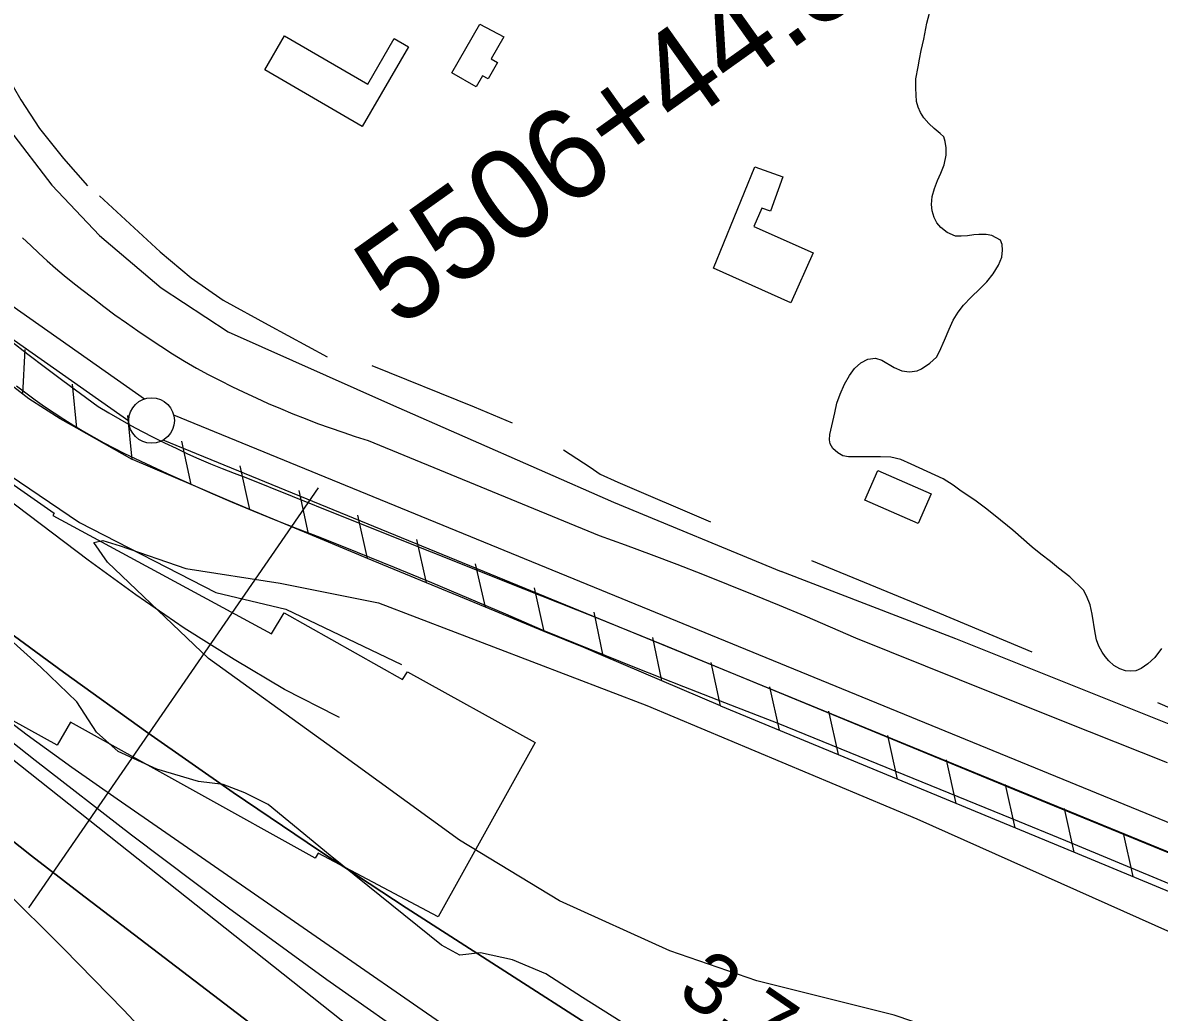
# Model space of a CAD drawing. Extents: x 3567028 to 3605064, y 510945 to 536587.
# Drawn here: x 3580256 to 3581504, y 529130 to 530217 of the extents above; entities that cross this region are included whole.
import ezdxf

# ---------------------------------------------------------------- set-up
doc = ezdxf.new("R2010")
doc.units = 0
for name, color, linetype in [('V-BLDG-OTLN', 7, 'Continuous'), ('V-FLOD-BASE', 7, 'Continuous'), ('V-LEVE-TOET', 7, 'Continuous'), ('V-RIVR-EDGE', 7, 'Continuous'), ('V-RIVR-RANG', 7, 'Continuous'), ('V-ROAD-CNTR', 7, 'Continuous'), ('V-RRAP-FSHR', 7, 'Continuous'), ('V-RRAP-RVMT', 7, 'Continuous'), ('V-SITE-VEGE', 7, 'Continuous'), ('V-SURV-IDEN', 7, 'Continuous'), ('V-SURV-LINE', 7, 'Continuous'), ('V-TOPO-DPTH', 7, 'Continuous'), ('V-TOPO-MINR', 7, 'Continuous'), ('V-TOPO-SHOR', 7, 'Continuous'), ('V-TOPO-WATR', 7, 'Continuous')]:
    doc.layers.add(name, color=color, linetype=linetype)

msp = doc.modelspace()

# ---------------------------------------------------------------- linework, layer by layer
at = {"layer": 'V-BLDG-OTLN'}
for points in [[(3580784.2, 530201), (3580770.2, 530176.8), (3580777.1, 530172.8), (3580766.7, 530154.8), (3580760.5, 530158.3), (3580753.6, 530146.3), (3580727, 530161.6), (3580757.8, 530214.9)], [(3580628.6, 530102.8), (3580521.8, 530164.8), (3580543.3, 530202), (3580634.6, 530149.1), (3580663.8, 530199.3), (3580679.4, 530190.2)], [(3581014.1, 529947), (3581059.6, 530058.3), (3581090.2, 530047.3), (3581076.8, 530009.8), (3581067.4, 530013), (3581058.5, 529992.9), (3581123.6, 529963.9), (3581099.2, 529909.2)], [(3581253.3, 529699.5), (3581238.9, 529666.8), (3581180.3, 529692.6), (3581194.6, 529725)]]:
    msp.add_lwpolyline(points, close=True, dxfattribs=at)
at = {"layer": 'V-FLOD-BASE'}
for points in [[(3580242.8, 529867.4), (3580261.7, 529852.7), (3580280.8, 529838.1), (3580299.9, 529823.7), (3580319.2, 529809.5), (3580338.6, 529795.4), (3580350.6, 529788.3), (3580362.6, 529781.3), (3580374.7, 529774.6), (3580386.9, 529768), (3580399.2, 529761.6), (3580411.6, 529755.4), (3580424.2, 529749.4), (3580436.8, 529743.5), (3580449.4, 529737.9), (3580462.2, 529732.4), (3580475, 529727.2), (3580488, 529722.1), (3580501, 529717.3), (3580602.5, 529676.4)], [(3580602.5, 529676.4), (3580704.2, 529635.8), (3580805.9, 529595.3), (3580883.5, 529564.3), (3580961, 529532.9), (3581038.3, 529501.3), (3581115.6, 529469.5), (3581232.6, 529421), (3581349.6, 529372.8), (3581466.8, 529324.8), (3581564, 529284.8), (3581661, 529244.7), (3581758, 529204.3), (3581854.8, 529163.6)]]:
    msp.add_lwpolyline(points, dxfattribs=at)
at = {"layer": 'V-LEVE-TOET'}
for points in [[(3580255.8, 529980.5), (3580264.7, 529971.9), (3580273.7, 529963.5), (3580282.8, 529955.2), (3580292.1, 529947.1), (3580301.5, 529939.2), (3580311, 529931.4), (3580320.7, 529923.8), (3580332.8, 529914.4), (3580344.9, 529905.1), (3580357.2, 529896), (3580369.7, 529887.1), (3580382.2, 529878.4), (3580394.9, 529869.8), (3580407.6, 529861.4), (3580420.5, 529853.2), (3580433.6, 529845.2), (3580446.7, 529837.3), (3580459.6, 529830.4), (3580472.6, 529823.7), (3580485.6, 529817.2), (3580498.8, 529810.9), (3580512.1, 529804.7), (3580525.4, 529798.7), (3580538.8, 529793), (3580552.4, 529787.4), (3580565.9, 529782), (3580579.6, 529776.8), (3580593.4, 529771.8), (3580607.2, 529767.1), (3580621, 529762.5), (3580635, 529758.1), (3580719.5, 529723.1), (3580804.1, 529688.4), (3580888.8, 529653.8), (3580917.2, 529643.4), (3580945.6, 529632.9), (3580973.9, 529622.1), (3581002.1, 529611.1), (3581030.3, 529600), (3581058.4, 529588.7), (3581086.3, 529577.1), (3581114.3, 529565.4), (3581142.1, 529553.5), (3581169.9, 529541.4), (3581284, 529495.8), (3581398.1, 529450.1), (3581512.3, 529404.5)], [(3580249.1, 529817.9), (3580259.3, 529810.2), (3580269.6, 529802.7), (3580280, 529795.4), (3580290.5, 529788.3), (3580301.2, 529781.3), (3580312, 529774.6), (3580322.9, 529768), (3580333.9, 529761.6), (3580345, 529755.4), (3580356.2, 529749.4), (3580367.6, 529743.6), (3580391, 529732.6), (3580414.6, 529721.7), (3580438.2, 529711.1), (3580461.9, 529700.6), (3580485.8, 529690.4), (3580509.7, 529680.4), (3580533.7, 529670.7), (3580557.8, 529661.1), (3580582, 529651.8), (3580623, 529635.4), (3580663.8, 529618.9), (3580704.6, 529602.1), (3580745.2, 529585), (3580785.8, 529567.8), (3580826.2, 529550.3), (3580877.8, 529529.3), (3580929.4, 529508.6), (3580981.1, 529488), (3581032.9, 529467.7), (3581084.7, 529447.6), (3581341.6, 529343.1), (3581400.6, 529319), (3581459.5, 529294.6), (3581518.4, 529270.1)]]:
    msp.add_lwpolyline(points, dxfattribs=at)
at = {"layer": 'V-RIVR-EDGE'}
msp.add_lwpolyline([(3580912.7, 529119.8), (3580870.5, 529146.8), (3580830.1, 529172.7), (3580793.4, 529188.1), (3580758.5, 529195.5), (3580735.8, 529193.1), (3580715.6, 529204.2), (3580593.3, 529302.5), (3580525.4, 529358.5), (3580499.7, 529371.4), (3580475.9, 529380.6), (3580448.9, 529383.8), (3580403, 529397.4), (3580360.8, 529416.5), (3580336.9, 529438), (3580315.5, 529471.1), (3580275.8, 529509.2), (3580204.3, 529573.1)], dxfattribs=at)
at = {"layer": 'V-RIVR-RANG'}
msp.add_line((3580580.2, 529706.1), (3580262.4, 529245), dxfattribs=at)
at = {"layer": 'V-ROAD-CNTR'}
for points in [[(3579390.6, 534604.7), (3579425.6, 534323.2), (3579477.9, 533896), (3579511.4, 533571.6), (3579529.4, 533437.4), (3579582.9, 533163.3), (3579675.1, 532684.9), (3579763.9, 532246.9), (3579878.2, 531633.7), (3579981.3, 531069.5), (3580080.1, 530529.2), (3580133.9, 530319.5), (3580158, 530251.5), (3580186.6, 530191.2), (3580216.7, 530137.7), (3580241.4, 530098.9), (3580287.8, 530038.4), (3580340.1, 529982.9), (3580407.9, 529925.4), (3580481.6, 529877.4), (3580659.6, 529797.7), (3580904.4, 529690.4), (3581088.3, 529614.1)], [(3583644.2, 528553.4), (3583147.5, 528757.7), (3582642.2, 528976.6), (3582349, 529100.4), (3582066.2, 529216.1), (3581964.5, 529257.9), (3581571.1, 529423.8), (3581280.2, 529540.2), (3581088.3, 529614.1)]]:
    msp.add_lwpolyline(points, dxfattribs=at)
at = {"layer": 'V-RRAP-FSHR'}
for p, q in [((3580256.2, 529808.9), (3580258.5, 529857.7)), ((3580315.3, 529771.4), (3580310.5, 529820)), ((3580376.2, 529737), (3580371.5, 529785.6)), ((3580440.7, 529709.7), (3580430.5, 529757.4)), ((3580505.2, 529682.4), (3580494.8, 529730.1)), ((3580569.7, 529655.4), (3580559.3, 529703.1)), ((3580634.3, 529628.4), (3580623.9, 529676.1)), ((3580699.1, 529601.8), (3580688.4, 529649.5)), ((3580763.8, 529575.2), (3580753.1, 529622.8)), ((3580828.5, 529548.5), (3580817.8, 529596.2)), ((3580893.1, 529521.6), (3580883.1, 529569.4)), ((3580957.5, 529494.1), (3580947.5, 529541.9)), ((3581021.9, 529466.6), (3581011.8, 529514.4)), ((3581086.6, 529439.9), (3581076, 529487.6)), ((3581151.3, 529413.2), (3581140.7, 529460.8)), ((3581216, 529386.4), (3581205.4, 529434.1)), ((3581280.7, 529359.7), (3581270.1, 529407.4)), ((3581345.4, 529333), (3581334.7, 529380.6)), ((3581410, 529306.2), (3581399.4, 529353.9)), ((3581474.7, 529279.4), (3581464.2, 529327.1))]:
    msp.add_line(p, q, dxfattribs=at)
for points in [[(3579617.5, 530621.7), (3579815.2, 530323), (3579894.6, 530194.1), (3579936.5, 530070.3), (3579998.1, 529936.5), (3580089.7, 529839.1), (3580197.6, 529749.5), (3580318.4, 529667.9), (3580467.8, 529591.2), (3580544.6, 529572.7), (3580671.9, 529512.1)], [(3580256.2, 529808.9), (3580200.8, 529851.7)], [(3580315.3, 529771.4), (3580297.1, 529781.6), (3580262.8, 529803.8), (3580256.2, 529808.9)], [(3580376.2, 529737), (3580315.3, 529771.4)], [(3580440.7, 529709.7), (3580376.3, 529737), (3580376.2, 529737)], [(3580505.2, 529682.4), (3580482.7, 529691.8), (3580440.7, 529709.7)], [(3580569.7, 529655.4), (3580505.2, 529682.4)], [(3580569.7, 529655.4), (3580569.2, 529655.6)], [(3580634.3, 529628.5), (3580624.8, 529632.4), (3580569.7, 529655.4)], [(3580699.1, 529601.8), (3580634.3, 529628.5)], [(3580763.8, 529575.2), (3580699.1, 529601.8)], [(3580828.5, 529548.5), (3580763.8, 529575.2)], [(3580893.1, 529521.6), (3580871.8, 529530.7), (3580828.5, 529548.5)], [(3580957.5, 529494.1), (3580893.1, 529521.6)], [(3581021.9, 529466.6), (3580957.5, 529494.1)], [(3581021.9, 529466.6), (3581409.4, 529306.5), (3582424.2, 528885), (3583566, 528409.8)]]:
    msp.add_lwpolyline(points, dxfattribs=at)
at = {"layer": 'V-RRAP-RVMT'}
for p, q in [((3580163.5, 529766.8), (3580290.6, 529678.2)), ((3580290.6, 529678.2), (3580288.9, 529675.8)), ((3580288.9, 529675.8), (3580528.9, 529545.8)), ((3580528.9, 529545.8), (3580543, 529568.9)), ((3580543, 529568.9), (3580672.9, 529495.7)), ((3580293.7, 529423.7), (3580162.9, 529496)), ((3580672.9, 529495.7), (3580678.3, 529504)), ((3580678.3, 529504), (3580818.6, 529426.5)), ((3580308.4, 529448.9), (3580293.7, 529423.7)), ((3580577.1, 529299.6), (3580308.4, 529448.9)), ((3580818.6, 529426.5), (3580711.9, 529235.1)), ((3580580.4, 529305.1), (3580577.1, 529299.6)), ((3580711.9, 529235.1), (3580580.4, 529305.1))]:
    msp.add_line(p, q, dxfattribs=at)
at = {"layer": 'V-SITE-VEGE'}
for points in [[(3581251.5, 529842.7), (3581258.8, 529849.6), (3581262.1, 529855.5), (3581267.8, 529868.1), (3581272.7, 529880.3), (3581277.4, 529890.1), (3581282.7, 529898.9), (3581288.6, 529906.6), (3581297.1, 529915.3), (3581306.7, 529924.5), (3581314.4, 529932.2), (3581321, 529940.8), (3581326.9, 529950.5), (3581330.8, 529959.1), (3581331.6, 529967), (3581331.2, 529973.1), (3581329.4, 529978), (3581319.8, 529983.1), (3581313.5, 529984.2), (3581305.5, 529984.2), (3581299.8, 529983.6), (3581293.1, 529982.5), (3581286, 529982.3), (3581279.7, 529982.3), (3581270.7, 529986.2), (3581263.6, 529991.9), (3581259.5, 529997), (3581256.5, 530002.9), (3581254.2, 530010.1), (3581253.6, 530017), (3581254.3, 530025.9), (3581256.9, 530034.5), (3581260.2, 530043.2), (3581263.8, 530051.4), (3581267.3, 530060.7), (3581269.6, 530071.3), (3581269.6, 530079.3), (3581268.4, 530086), (3581266.9, 530091.3), (3581262.9, 530095), (3581256.4, 530100.3), (3581250.4, 530106), (3581245, 530112.3), (3581241.3, 530118), (3581238.9, 530123.7), (3581237, 530130.2), (3581236.2, 530144.7), (3581236.4, 530154.8), (3581238.7, 530168.1), (3581240.3, 530176.4), (3581242.2, 530186), (3581245, 530198.6), (3581248.3, 530215.9), (3581251.2, 530226.9)], [(3581505.9, 529529.7), (3581498.6, 529519.8), (3581491.1, 529512.7), (3581483.5, 529507.8), (3581477.8, 529505.3), (3581472.3, 529504.7), (3581466.4, 529505.3), (3581460.3, 529507.4), (3581453.8, 529510.9), (3581448.3, 529516.1), (3581444, 529520.8), (3581440.8, 529525.7), (3581437.1, 529532.2), (3581434.5, 529539.2), (3581433.1, 529546.9), (3581429.8, 529567.3), (3581427.6, 529577.5), (3581423.5, 529587.6), (3581420.5, 529593.7), (3581405.4, 529608.2), (3581393, 529617.8), (3581384, 529625.3), (3581373.5, 529633.1), (3581363.9, 529640.8), (3581342.7, 529659.6), (3581323.2, 529675.3), (3581312.6, 529683.6), (3581301, 529692.6), (3581286, 529702.4), (3581277.4, 529709.1), (3581266.2, 529716), (3581231, 529732.1), (3581220, 529737), (3581209, 529739.7), (3581197.6, 529740.1), (3581187.2, 529739.9), (3581162.2, 529739.9), (3581156.3, 529741.2), (3581150.8, 529744.4), (3581145.1, 529749.1), (3581142.3, 529754.2), (3581141.5, 529758.9), (3581141.9, 529764.6), (3581147.2, 529788.2), (3581149.4, 529798.8), (3581153.3, 529809), (3581158, 529820), (3581163.5, 529829.3), (3581169, 529837.1), (3581175.9, 529843.4), (3581183.5, 529847.2), (3581192, 529848.4), (3581199.1, 529846.2), (3581212.4, 529838.2), (3581221.1, 529834.4), (3581229.5, 529833.5), (3581237.8, 529834.6), (3581242.5, 529836.6), (3581251.5, 529842.7)], [(3581579.9, 528990.8), (3581374.3, 529072.4), (3581212.6, 529127.2), (3581061.9, 529165), (3580966.1, 529197.8), (3580845.3, 529252.6), (3580735.5, 529319.3), (3580589.7, 529424.9), (3580459.9, 529518.6), (3580349, 529624.3), (3580334.1, 529646.2), (3580344, 529648.2), (3580363, 529642.3), (3580434.9, 529617.4), (3580538.6, 529601.5), (3580646.4, 529579.7), (3580940.9, 529467.2), (3581237.3, 529342.7), (3581515.8, 529218.3)]]:
    msp.add_lwpolyline(points, dxfattribs=at)
at = {"layer": 'V-SURV-LINE'}
for points in [[(3580200.4, 529936.6), (3580389.6, 529803.7)], [(3580372.4, 529779.1), (3580183.2, 529912)], [(3580421.6, 529786.2), (3581903.9, 529178.8)], [(3581892.5, 529151.1), (3580410.2, 529758.5)]]:
    msp.add_lwpolyline(points, dxfattribs=at)
msp.add_circle((3580397.4, 529779.9), 25, dxfattribs=at)
at = {"layer": 'V-TOPO-DPTH'}
for points in [[(3580148.4, 529615.4), (3580300.7, 529503.8), (3580393.4, 529437.1), (3580486.9, 529371.6), (3580581.6, 529307.8), (3580677, 529245.2), (3580992.6, 529042.3)], [(3580699.1, 529089.3), (3580589.9, 529166.2), (3580481.8, 529244.6), (3580375.3, 529324.9), (3580269.7, 529406.7), (3580081.2, 529555.6)], [(3580699.1, 529089.3), (3580589.9, 529166.2), (3580481.8, 529244.6), (3580375.3, 529324.9), (3580269.7, 529406.7), (3580081.2, 529555.6)], [(3580213.7, 529343.2), (3580265.7, 529302), (3580318.1, 529261.4), (3580823.1, 528875.8)], [(3580823.1, 528875.8), (3580318.1, 529261.4), (3580265.7, 529302), (3580213.7, 529343.2)], [(3580233.8, 529267), (3580300.8, 529200.3), (3580366.9, 529132.8), (3580431.4, 529063.8)], [(3580431.4, 529063.8), (3580366.9, 529132.8), (3580300.8, 529200.3), (3580233.8, 529267)]]:
    msp.add_lwpolyline(points, dxfattribs=at)
at = {"layer": 'V-TOPO-MINR'}
for points in [[(3580603.5, 529454.1), (3580600.6, 529455.4), (3580543.3, 529484.7), (3580487.9, 529517.7), (3580433.3, 529552.1), (3580380.1, 529588.6), (3580327.8, 529626.5), (3580210, 529715.5), (3580201.5, 529722.4), (3580193.3, 529729.7), (3580185.7, 529737.5), (3580178.5, 529745.6), (3580124.6, 529810.9), (3580091.1, 529852.3), (3580058.2, 529894.2)], [(3580699.1, 529089.3), (3580589.9, 529166.2), (3580481.8, 529244.6), (3580375.3, 529324.9), (3580269.7, 529406.7), (3580081.2, 529555.6)], [(3580616.2, 529113.5), (3580083.2, 529535.6)], [(3580942.4, 528961.1), (3580359.5, 529364.2), (3580310, 529399.2), (3580260.9, 529434.7), (3580212.5, 529471.2)], [(3580823.1, 528875.8), (3580318.1, 529261.4), (3580265.7, 529302), (3580213.7, 529343.2)], [(3580431.4, 529063.8), (3580366.9, 529132.8), (3580300.8, 529200.3), (3580233.8, 529267)]]:
    msp.add_lwpolyline(points, dxfattribs=at)
at = {"layer": 'V-TOPO-SHOR'}
for p, q in [((3580300.8, 530067.5), (3580327, 530037.5)), ((3581570.7, 529440.7), (3581501.8, 529470))]:
    msp.add_line(p, q, dxfattribs=at)
for points in [[(3580186.4, 530264.5), (3580219.9, 530190.6), (3580253.8, 530132), (3580274.5, 530100.6), (3580300.8, 530067.5)], [(3580340.1, 530026.6), (3580406.7, 529965.1), (3580440.7, 529936.6), (3580475.9, 529912), (3580525.2, 529885.1), (3580590, 529849.9)], [(3580639, 529840.2), (3580751.6, 529794.9), (3580793.1, 529777.5)], [(3580849.4, 529747.9), (3580878.7, 529728.7), (3580889.9, 529721.1), (3580909.1, 529712.4), (3581011, 529668.7)], [(3581121.6, 529626.1), (3581262.3, 529568.3), (3581363.7, 529526.2)]]:
    msp.add_lwpolyline(points, dxfattribs=at)
at = {"layer": 'V-TOPO-WATR'}
msp.add_lwpolyline([(3580992.6, 529042.3), (3580677, 529245.2), (3580581.6, 529307.8), (3580486.9, 529371.6), (3580393.4, 529437.1), (3580300.7, 529503.8), (3580148.4, 529615.4)], dxfattribs=at)

# ---------------------------------------------------------------- texts
at = {"layer": 'V-RIVR-RANG'}
msp.add_text('3.7', height=67, rotation=325.4583, dxfattribs=at).set_placement((3580972.3, 529148.2))
at = {"layer": 'V-SURV-IDEN'}
msp.add_text('5506+44.5', height=100, rotation=35.4497, dxfattribs=at).set_placement((3580668.6, 529879.8))

doc.saveas('drawing.dxf')
